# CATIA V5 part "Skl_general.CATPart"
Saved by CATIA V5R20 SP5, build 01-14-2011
Part number: Skl_general
Publications: "Long_Total", "Larg_Totale", "Point.1", "Point.2", "Point.3", "Point.4", "Point.5", "Point.6", "Point.7", "Point.8", "Point.9", "Point.10", "Point.11", "Point.12", "Point.13", "Point.14", "Point.15", "Point.16", "Point.17", "Point.18", "Point.19", "Point.20", "Point.21", "Point.23", "Point.24", "Point.22", "Point.25", "Plan_xy-10mm"
Bounding box of the stored display mesh (mm): x 0 to 0, y 0 to 450, z -1100 to 150
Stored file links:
  U:\2A\CFAO\dossier sans titre\Skl_general.CATPart
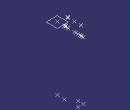
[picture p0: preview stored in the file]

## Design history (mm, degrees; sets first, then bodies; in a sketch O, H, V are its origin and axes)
Parameters
  Long_Total = 1100 mm
  Larg_Totale = 450 mm
Set1
  Point1: (0, 0, 0)
  Point2: (0, 122.7273 {= (3/11)*Larg_Totale}, 0)
  Point3: (0, 142.7273 {= (3/11)*Larg_Totale +(20/450)*Larg_Totale}, 0)
  Point4: (0, 152.7273 {= (3/11)*Larg_Totale +(30/450)*Larg_Totale}, 0)
  Point5: (0, 182.7273 {= (3/11)*Larg_Totale +(60/450)*Larg_Totale}, 0)
  Point6: (0, 182.7273 {= Point5.Y}, 150)
  Point7: (0, 187.7273 {= Point6.Y +5mm}, 150 {= Point6.Z})
  Point8: (0, 122.7273 {= (3/11)*Larg_Totale}, -10)
  Point9: (0, 360 {= Larg_Totale -(90/450)*Larg_Totale}, -10)
  Point10: (0, 450 {= Larg_Totale}, -10)
  Point11: (0, 325 {= Larg_Totale -(90/450)*Larg_Totale -(35/450)*Larg_Totale}, -10)
  Point12: (0, 430 {= Larg_Totale -(20/450)*Larg_Totale}, -10)
  Point13: (0, 390 {= Larg_Totale - (60/450)*Larg_Totale}, -10)
  Point14: (0, 415 {= Larg_Totale -(90/450)*Larg_Totale +(50/450)*Larg_Totale+5mm}, 150)
  Point15: (0, 0, -1100 {= -Long_Total})
  Point16: (0, 122.7273 {= (3/11)*Larg_Totale}, -1100 {= -Long_Total})
  Point17: (0, 360 {= Larg_Totale -(90/450)*Larg_Totale}, -1100 {= -Long_Total})
  Point18: (0, 360 {= Larg_Totale -(90/450)*Larg_Totale}, -1010 {= -(1010/1100)*Long_Total})
  Point19: (0, 450 {= Larg_Totale}, -1010 {= -(1010/1100)*Long_Total})
  Point20: (0, 415 {= Larg_Totale -(90/450)*Larg_Totale +(50/450)*Larg_Totale+5mm}, -10)
  Point21: (0, 410 {= Larg_Totale -(90/450)*Larg_Totale +(50/450)*Larg_Totale}, 150)
  Point22: (0, 187.7273 {= Point7.Y}, -10)
  Point23 "Point.23": (0, 111.1365 {= ((405/450)*Larg_Totale -( 182.727/450)*Larg_Totale)/2}, 0), relative to Point22
  Point24 "Point.24": (0, 111.1365 {= Point23.Y}, 160), relative to Point22
  Point25 "Point.25": (0, 177.7273 {= Point6.Y -5mm}, 150)
  Plane1 "Plan_xy-10mm": type Offset, RefPlane xy-plane, Offset -10
Body1 (main body)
